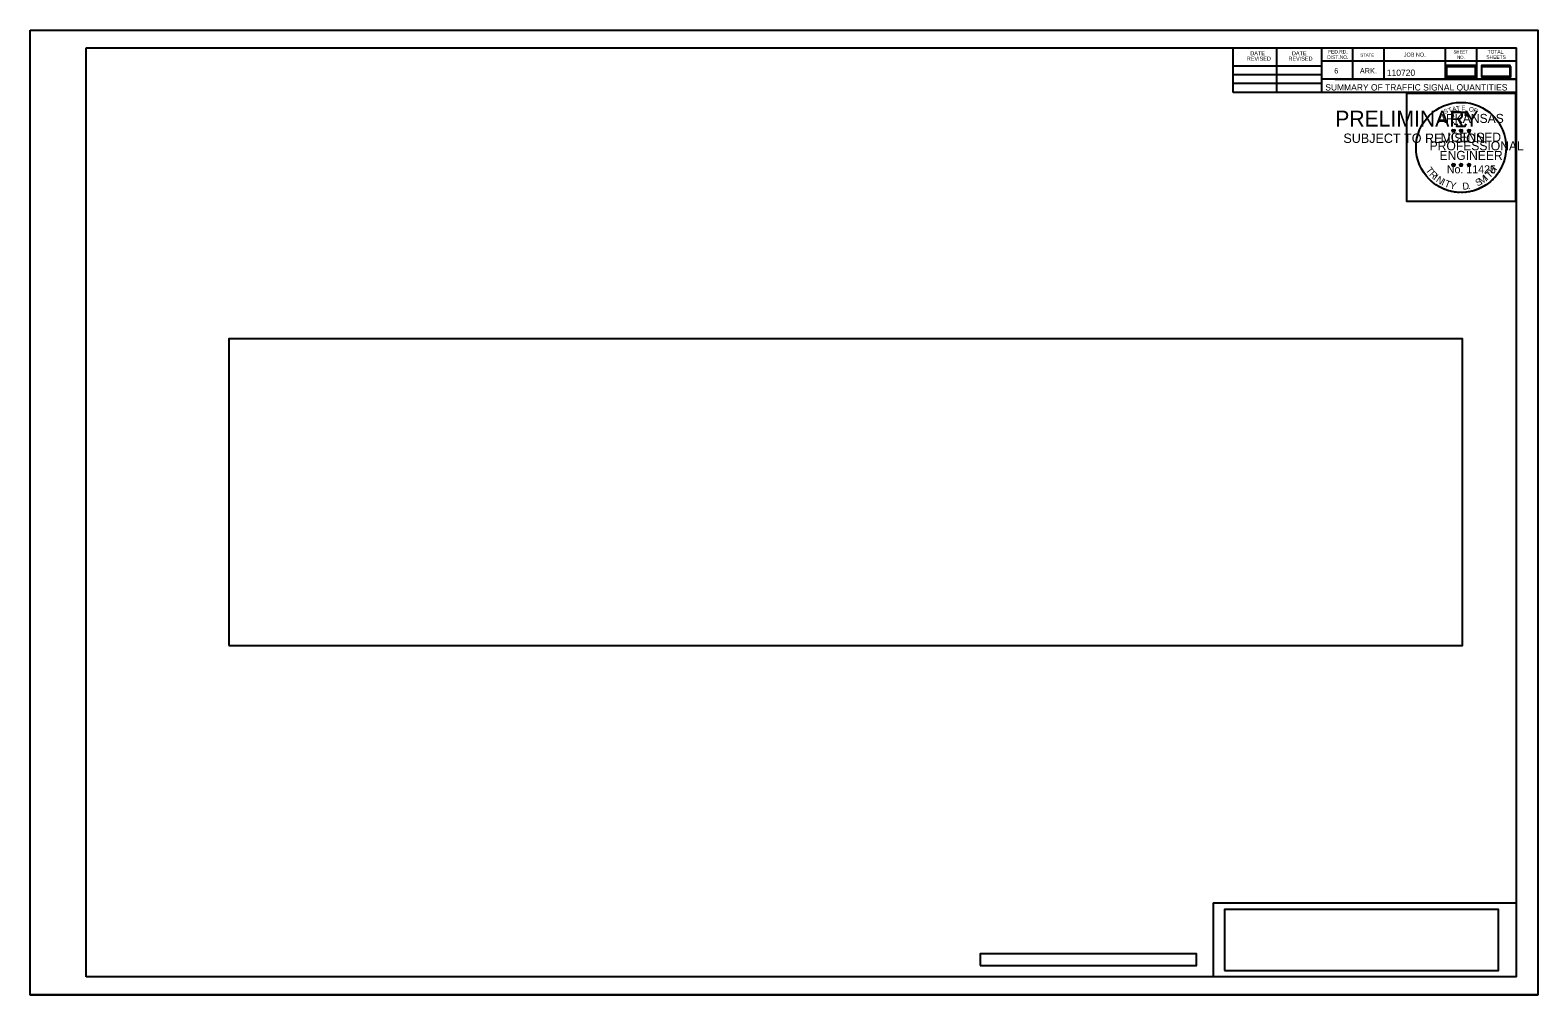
# Model space of a CAD drawing. Extents: x 1370022 to 1370689, y 379972 to 380399.
import ezdxf

# ---------------------------------------------------------------- set-up
doc = ezdxf.new("R2010")
doc.units = 0
for name, color, linetype in [('Default', 7, 'Continuous'), ('Level 1', 7, 'Continuous'), ('Level 2', 7, 'Continuous'), ('Level 3', 7, 'Continuous'), ('Level 4', 7, 'Continuous'), ('Level 5', 7, 'Continuous'), ('Level 6', 7, 'Continuous')]:
    doc.layers.add(name, color=color, linetype=linetype)

msp = doc.modelspace()

# ---------------------------------------------------------------- linework, layer by layer
at = {"layer": 'Default'}
for points in [[(1370648.78, 380378.37), (1370661.48, 380378.37), (1370661.48, 380383.06), (1370648.78, 380383.06)], [(1370664.17, 380378.37), (1370676.87, 380378.37), (1370676.87, 380383.06), (1370664.17, 380383.06)], [(1370110.3, 380126.54), (1370655.8, 380126.54), (1370655.8, 380262.2), (1370110.3, 380262.2)], [(1370550.63, 379982.78), (1370671.67, 379982.78), (1370671.67, 380009.76), (1370550.63, 380009.76)], [(1370442.54, 379985.01), (1370538.24, 379985.01), (1370538.24, 379990.18), (1370442.54, 379990.18)]]:
    msp.add_lwpolyline(points, close=True, dxfattribs=at)
at = {"layer": 'Level 1'}
for points in [[(1370545.57, 380012.69), (1370679.62, 380012.69)], [(1370545.57, 380012.69), (1370545.57, 379980)]]:
    msp.add_lwpolyline(points, dxfattribs=at)
at = {"layer": 'Level 2'}
for p, q in [((1370047.26, 380390.92), (1370679.62, 380390.92)), ((1370047.26, 379980), (1370047.26, 380390.92)), ((1370352.3, 380390.4), (1370352.3, 380390.4)), ((1370352.3, 380390.4), (1370352.3, 380390.4)), ((1370554.34, 380371.16), (1370554.34, 380390.92)), ((1370573.7, 380371.16), (1370573.7, 380390.92)), ((1370593.42, 380390.92), (1370593.42, 380371.16)), ((1370607.1, 380390.92), (1370607.1, 380377.04)), ((1370620.98, 380390.92), (1370620.98, 380377.04)), ((1370648.14, 380390.92), (1370648.14, 380377.04)), ((1370662.02, 380390.92), (1370662.02, 380377.04)), ((1370679.62, 379980), (1370679.62, 380390.92)), ((1370554.34, 380382.88), (1370593.42, 380382.88)), ((1370679.62, 380385.04), (1370593.42, 380385.04)), ((1370679.62, 380385.08), (1370679.62, 380385.08)), ((1370554.34, 380379.16), (1370593.42, 380379.16)), ((1370554.34, 380375.28), (1370593.42, 380375.28)), ((1370679.62, 380377.04), (1370593.42, 380377.04)), ((1370599.34, 380377.04), (1370679.62, 380377.04)), ((1370679.62, 380371.16), (1370554.34, 380371.16)), ((1370047.26, 379980), (1370047.26, 379980)), ((1370679.62, 379980), (1370047.26, 379980))]:
    msp.add_line(p, q, dxfattribs=at)
at = {"layer": 'Level 3'}
for p, q in [((1370022.46, 380398.71), (1370689.12, 380398.71)), ((1370631.03, 380325.07), (1370631.03, 380325.07)), ((1370022.46, 379972.05), (1370689.12, 379972.05))]:
    msp.add_line(p, q, dxfattribs=at)
for points in [[(1370022.44, 380398.71), (1370689.12, 380398.71), (1370689.12, 379972.04), (1370022.44, 379972.04)], [(1370631.18, 380370.86), (1370679.18, 380370.86), (1370679.18, 380322.86), (1370631.18, 380322.86)]]:
    msp.add_lwpolyline(points, close=True, dxfattribs=at)
msp.add_circle((1370655.18, 380346.86), 19.9, dxfattribs=at)
at = {"layer": 'Level 5'}
for p, q in [((1370651.13, 380354.49), (1370651.83, 380354.26)), ((1370651.13, 380354.49), (1370651.64, 380354.4)), ((1370651.13, 380354.49), (1370651.6, 380354.24)), ((1370651.83, 380354.99), (1370651.75, 380354.49)), ((1370651.83, 380354.26), (1370651.83, 380354.99)), ((1370651.83, 380354.99), (1370651.93, 380354.49)), ((1370652.52, 380354.49), (1370651.83, 380354.26)), ((1370652.52, 380354.49), (1370651.95, 380354.39)), ((1370652.52, 380354.49), (1370652.11, 380354.28)), ((1370654.47, 380354.49), (1370655.17, 380354.26)), ((1370654.47, 380354.49), (1370654.98, 380354.4)), ((1370654.47, 380354.49), (1370654.94, 380354.24)), ((1370655.17, 380354.99), (1370655.09, 380354.49)), ((1370655.17, 380354.26), (1370655.17, 380354.99)), ((1370655.17, 380354.99), (1370655.27, 380354.49)), ((1370655.86, 380354.49), (1370655.17, 380354.26)), ((1370655.86, 380354.49), (1370655.29, 380354.39)), ((1370655.86, 380354.49), (1370655.45, 380354.28)), ((1370658, 380354.46), (1370658.7, 380354.24)), ((1370658, 380354.46), (1370658.5, 380354.37)), ((1370658, 380354.46), (1370658.47, 380354.22)), ((1370658.7, 380354.97), (1370658.61, 380354.47)), ((1370658.7, 380354.24), (1370658.7, 380354.97)), ((1370658.7, 380354.97), (1370658.79, 380354.47)), ((1370659.39, 380354.46), (1370658.7, 380354.24)), ((1370659.39, 380354.46), (1370658.82, 380354.36)), ((1370659.39, 380354.46), (1370658.98, 380354.26)), ((1370651.4, 380353.67), (1370651.83, 380354.26)), ((1370651.4, 380353.67), (1370651.65, 380354.16)), ((1370651.4, 380353.67), (1370651.82, 380354.1)), ((1370652.25, 380353.67), (1370651.82, 380354.1)), ((1370652.25, 380353.67), (1370651.83, 380354.26)), ((1370652.25, 380353.67), (1370651.98, 380354.25)), ((1370654.74, 380353.67), (1370655.17, 380354.26)), ((1370654.74, 380353.67), (1370654.99, 380354.16)), ((1370654.74, 380353.67), (1370655.16, 380354.1)), ((1370655.59, 380353.67), (1370655.16, 380354.1)), ((1370655.59, 380353.67), (1370655.17, 380354.26)), ((1370655.59, 380353.67), (1370655.32, 380354.25)), ((1370658.26, 380353.65), (1370658.7, 380354.24)), ((1370658.26, 380353.65), (1370658.52, 380354.13)), ((1370658.26, 380353.65), (1370658.69, 380354.08)), ((1370659.12, 380353.65), (1370658.69, 380354.07)), ((1370659.12, 380353.65), (1370658.7, 380354.24)), ((1370659.12, 380353.65), (1370658.85, 380354.23)), ((1370651.12, 380339.34), (1370651.82, 380339.12)), ((1370651.12, 380339.34), (1370651.63, 380339.25)), ((1370651.12, 380339.34), (1370651.6, 380339.1)), ((1370651.39, 380338.52), (1370651.82, 380339.12)), ((1370651.39, 380338.52), (1370651.64, 380339.01)), ((1370651.39, 380338.52), (1370651.82, 380338.96)), ((1370651.82, 380339.85), (1370651.74, 380339.34)), ((1370651.82, 380339.12), (1370651.82, 380339.85)), ((1370651.82, 380339.85), (1370651.92, 380339.35)), ((1370652.51, 380339.34), (1370651.82, 380339.12)), ((1370652.25, 380338.52), (1370651.82, 380339.12)), ((1370652.25, 380338.52), (1370651.82, 380338.95)), ((1370652.51, 380339.34), (1370651.94, 380339.24)), ((1370652.25, 380338.52), (1370651.97, 380339.11)), ((1370652.51, 380339.34), (1370652.11, 380339.14)), ((1370654.46, 380339.34), (1370655.16, 380339.12)), ((1370654.46, 380339.34), (1370654.97, 380339.25)), ((1370654.46, 380339.34), (1370654.93, 380339.1)), ((1370654.73, 380338.52), (1370655.16, 380339.12)), ((1370654.73, 380338.52), (1370654.98, 380339.01)), ((1370654.73, 380338.52), (1370655.15, 380338.96)), ((1370655.16, 380339.85), (1370655.08, 380339.34)), ((1370655.58, 380338.52), (1370655.15, 380338.95)), ((1370655.16, 380339.12), (1370655.16, 380339.85)), ((1370655.16, 380339.85), (1370655.26, 380339.35)), ((1370655.85, 380339.34), (1370655.16, 380339.12)), ((1370655.58, 380338.52), (1370655.16, 380339.12)), ((1370655.85, 380339.34), (1370655.28, 380339.24)), ((1370655.58, 380338.52), (1370655.31, 380339.11)), ((1370655.85, 380339.34), (1370655.44, 380339.14)), ((1370657.99, 380339.32), (1370658.69, 380339.1)), ((1370657.99, 380339.32), (1370658.5, 380339.23)), ((1370657.99, 380339.32), (1370658.47, 380339.08)), ((1370658.26, 380338.5), (1370658.69, 380339.1)), ((1370658.26, 380338.5), (1370658.51, 380338.99)), ((1370658.26, 380338.5), (1370658.69, 380338.94)), ((1370658.69, 380339.83), (1370658.61, 380339.32)), ((1370658.69, 380339.1), (1370658.69, 380339.83)), ((1370658.69, 380339.83), (1370658.79, 380339.33)), ((1370659.39, 380339.32), (1370658.69, 380339.1)), ((1370659.12, 380338.5), (1370658.69, 380339.1)), ((1370659.12, 380338.5), (1370658.69, 380338.93)), ((1370659.39, 380339.32), (1370658.81, 380339.22)), ((1370659.12, 380338.5), (1370658.84, 380339.09)), ((1370659.39, 380339.32), (1370658.98, 380339.12))]:
    msp.add_line(p, q, dxfattribs=at)
for points in [[(1370651.21, 380362.24), (1370651.75, 380360.59)], [(1370658.23, 380360.4), (1370658.52, 380360.97), (1370657.15, 380360.92), (1370657.44, 380362.24), (1370651.21, 380362.24)], [(1370651.83, 380354.99), (1370652.25, 380353.67), (1370651.13, 380354.49), (1370652.52, 380354.49), (1370651.4, 380353.67), (1370651.83, 380354.99)], [(1370652.2, 380357.4), (1370652.2, 380357.22), (1370653.32, 380357.18), (1370653.21, 380356.24), (1370656.95, 380356.24), (1370657.36, 380357.31)], [(1370655.17, 380354.99), (1370655.59, 380353.67), (1370654.47, 380354.49), (1370655.86, 380354.49), (1370654.74, 380353.67), (1370655.17, 380354.99)], [(1370658.7, 380354.97), (1370659.12, 380353.65), (1370658, 380354.46), (1370659.39, 380354.46), (1370658.26, 380353.65), (1370658.7, 380354.97)], [(1370651.82, 380339.85), (1370652.25, 380338.52), (1370651.12, 380339.34), (1370652.51, 380339.34), (1370651.39, 380338.52), (1370651.82, 380339.85)], [(1370655.16, 380339.85), (1370655.58, 380338.52), (1370654.46, 380339.34), (1370655.85, 380339.34), (1370654.73, 380338.52), (1370655.16, 380339.85)], [(1370658.69, 380339.83), (1370659.12, 380338.5), (1370657.99, 380339.32), (1370659.39, 380339.32), (1370658.26, 380338.5), (1370658.69, 380339.83)]]:
    msp.add_lwpolyline(points, dxfattribs=at)
for centre, radius in [((1370651.83, 380354.26), 0.344), ((1370651.83, 380354.26), 0.289), ((1370651.83, 380354.26), 0.231), ((1370651.83, 380354.26), 0.198), ((1370651.83, 380354.26), 0.149), ((1370651.83, 380354.26), 0.0991), ((1370651.83, 380354.26), 0.0593), ((1370655.17, 380354.26), 0.344), ((1370655.17, 380354.26), 0.289), ((1370655.17, 380354.26), 0.231), ((1370655.17, 380354.26), 0.198), ((1370655.17, 380354.26), 0.149), ((1370655.17, 380354.26), 0.0991), ((1370655.17, 380354.26), 0.0593), ((1370658.69, 380354.24), 0.344), ((1370658.69, 380354.24), 0.289), ((1370658.69, 380354.24), 0.231), ((1370658.69, 380354.24), 0.198), ((1370658.69, 380354.24), 0.149), ((1370658.69, 380354.24), 0.0991), ((1370658.69, 380354.24), 0.0593), ((1370651.82, 380339.12), 0.344), ((1370651.82, 380339.12), 0.289), ((1370651.82, 380339.12), 0.231), ((1370651.82, 380339.12), 0.198), ((1370651.82, 380339.12), 0.149), ((1370651.82, 380339.12), 0.0991), ((1370651.82, 380339.12), 0.0593), ((1370655.16, 380339.12), 0.344), ((1370655.16, 380339.12), 0.289), ((1370655.16, 380339.12), 0.231), ((1370655.16, 380339.12), 0.198), ((1370655.16, 380339.12), 0.149), ((1370655.16, 380339.12), 0.0991), ((1370655.16, 380339.12), 0.0593), ((1370658.69, 380339.1), 0.344), ((1370658.69, 380339.1), 0.289), ((1370658.69, 380339.1), 0.231), ((1370658.69, 380339.1), 0.198), ((1370658.69, 380339.1), 0.149), ((1370658.69, 380339.1), 0.0991), ((1370658.69, 380339.1), 0.0593)]:
    msp.add_circle(centre, radius, dxfattribs=at)
at = {"layer": 'Level 6'}
for points in [[(1370648.76, 380382.58), (1370661.45, 380382.58), (1370661.45, 380377.89), (1370648.76, 380377.89)], [(1370664.39, 380382.58), (1370677.09, 380382.58), (1370677.09, 380377.89), (1370664.39, 380377.89)]]:
    msp.add_lwpolyline(points, close=True, dxfattribs=at)

# ---------------------------------------------------------------- texts
at = {"layer": 'Level 2'}
for s, height, p in [('DATE', 1.758, (1370561.98, 380387.6)), ('DATE', 1.758, (1370580.39, 380387.6)), ('FED.RD.', 1.564, (1370596.38, 380388.36)), ('STATE', 1.368, (1370610.62, 380387)), ('JOB NO.', 1.758, (1370629.82, 380387)), ('SHEET', 1.368, (1370651.86, 380388.36)), ('TOTAL', 1.564, (1370666.9, 380388.36)), ('REVISED', 1.758, (1370560.42, 380385.24)), ('REVISED', 1.758, (1370578.83, 380385.24)), ('DIST.NO.', 1.564, (1370595.98, 380386)), ('6', 2.34, (1370599.1, 380379.56)), ('ARK.', 2.345, (1370610.42, 380379.56)), ('110720', 2.8, (1370622.37, 380378.48)), ('NO.', 1.368, (1370653.42, 380386)), ('SHEETS', 1.564, (1370666.34, 380386)), ('SUMMARY OF TRAFFIC SIGNAL QUANTITIES', 2.8, (1370595.14, 380372.02))]:
    msp.add_text(s, height=height, dxfattribs=at).set_placement(p)
at = {"layer": 'Level 4'}
for s, height, p in [('PRELIMINARY', 7, (1370599.52, 380356.09)), ('SUBJECT TO REVISION', 4.1502, (1370603.14, 380348.83))]:
    msp.add_text(s, height=height, dxfattribs=at).set_placement(p)
at = {"layer": 'Level 5'}
for s, height, rotation, p in [('-', 3.2, 48.42305, (1370641.11, 380359.25)), ('-', 3.2, 42.96224, (1370642.01, 380360.2)), ('-', 3.2, 38.95066, (1370642.87, 380361.04)), ('-', 3.2, 36.23174, (1370643.82, 380361.79)), ('-', 3.2, 34.06357, (1370644.98, 380362.58)), ('-', 3.2, 28.79182, (1370646.17, 380363.32)), ('-', 3.2, 24.30721, (1370647.44, 380363.96)), ('S', 2, 21.59401, (1370647.92, 380361.6)), ('-', 3.2, 19.17608, (1370648.71, 380364.5)), ('T', 2, 16.4036, (1370649.75, 380362.26)), ('-', 3.2, 13.63015, (1370650.21, 380364.98)), ('A', 2, 11.21318, (1370651.4, 380362.76)), ('-', 3.2, 10.21935, (1370651.56, 380365.3)), ('T', 2, 6.02276, (1370653.1, 380363.09)), ('-', 3.2, 5.89682, (1370653.02, 380365.52)), ('-', 3.2, 0.18623, (1370654.57, 380365.67)), ('E', 2, 0.83234, (1370655.31, 380363.31)), ('-', 3.2, 357.74304, (1370656.01, 380365.64)), ('-', 3.2, 352.16172, (1370657.5, 380365.53)), ('O', 2, 350.4515, (1370658.52, 380362.89)), ('-', 3.2, 347.20489, (1370658.94, 380365.3)), ('F', 2, 340.07066, (1370660.43, 380362.44)), ('-', 3.2, 342.3362, (1370660.21, 380364.99)), ('-', 3.2, 337.85509, (1370661.68, 380364.54)), ('-', 3.2, 334.12109, (1370662.94, 380364)), ('-', 3.2, 329.64089, (1370664.1, 380363.44)), ('-', 3.2, 325.86266, (1370665.38, 380362.71)), ('-', 3.2, 320.52971, (1370666.6, 380361.86)), ('-', 3.2, 315.57859, (1370667.8, 380360.89)), ('-', 3.2, 67.77427, (1370637.68, 380353.64)), ('-', 3.2, 62.87135, (1370638.2, 380354.86)), ('-', 3.2, 58.07063, (1370638.83, 380356.09)), ('-', 3.2, 54.23247, (1370639.48, 380357.14)), ('-', 3.2, 50.61417, (1370640.3, 380358.28)), ('-', 3.2, 309.87973, (1370668.94, 380359.79)), ('-', 3.2, 306.65218, (1370669.99, 380358.58)), ('-', 2.8, 303.67529, (1370670.96, 380357.45)), ('-', 3.2, 299.66835, (1370671.6, 380356.23)), ('-', 3.2, 294.66279, (1370672.25, 380355.01)), ('-', 3.2, 89.06224, (1370636.39, 380346.74)), ('-', 3.2, 85.18634, (1370636.44, 380348.14)), ('-', 3.2, 81.20126, (1370636.59, 380349.52)), ('-', 3.2, 75.46096, (1370636.85, 380350.95)), ('-', 3.2, 72.39447, (1370637.25, 380352.38)), ('-', 3.2, 290.57283, (1370672.76, 380353.85)), ('-', 3.2, 285.12326, (1370673.23, 380352.69)), ('-', 3.2, 280.54934, (1370673.63, 380351.21)), ('-', 3.2, 276.59616, (1370673.95, 380349.67)), ('-', 3.2, 274.33011, (1370674.07, 380348.23)), ('-', 3.2, 94.19588, (1370636.46, 380345.29)), ('-', 3.2, 98.94793, (1370636.6, 380343.96)), ('-', 3.2, 101.71495, (1370636.87, 380342.49)), ('-', 3.2, 105.45785, (1370637.19, 380341.3)), ('-', 3.2, 252.86809, (1370673.38, 380341.53)), ('-', 3.2, 255.7626, (1370673.74, 380342.97)), ('-', 3.2, 260.99529, (1370673.96, 380344.33)), ('-', 3.2, 263.5172, (1370674.1, 380345.63)), ('-', 3.2, 269.94067, (1370674.14, 380346.97)), ('-', 3.2, 109.08742, (1370637.62, 380340.04)), ('-', 3.2, 114.06432, (1370638.13, 380338.85)), ('-', 3.2, 115.72885, (1370638.74, 380337.61)), ('-', 3.2, 120.44712, (1370639.46, 380336.44)), ('-', 3.2, 125.89344, (1370640.26, 380335.32)), ('-', 3.2, 130.71812, (1370641.19, 380334.21)), ('T', 3.08, 306.04056, (1370639.34, 380336.79)), ('R', 3.08, 314.00497, (1370640.86, 380334.7)), ('I', 3.08, 321.96938, (1370642.66, 380332.84)), ('N', 3.08, 326.50021, (1370643.8, 380331.89)), ('M', 3.08, 32.65632, (1370664.11, 380330.33)), ('I', 3.08, 42.11359, (1370666.68, 380332.02)), ('T', 3.08, 46.64442, (1370667.8, 380332.98)), ('H', 3.08, 54.60883, (1370669.58, 380334.87)), ('-', 3.2, 233.84524, (1370670.82, 380336.12)), ('-', 3.2, 239.07125, (1370671.62, 380337.42)), ('-', 3.2, 244.61971, (1370672.41, 380338.93)), ('-', 3.2, 247.88866, (1370672.93, 380340.18)), ('-', 3.2, 134.22381, (1370642.22, 380333.12)), ('-', 3.2, 138.93382, (1370643.27, 380332.19)), ('-', 3.2, 144.64634, (1370644.38, 380331.38)), ('-', 3.2, 148.08978, (1370645.5, 380330.64)), ('-', 3.2, 151.57039, (1370646.66, 380329.99)), ('-', 3.2, 154.60019, (1370647.71, 380329.5)), ('I', 3.08, 335.36034, (1370646.22, 380330.32)), ('-', 3.2, 158.56121, (1370648.95, 380328.99)), ('T', 3.08, 339.89117, (1370647.54, 380329.67)), ('-', 3.2, 162.79826, (1370650.33, 380328.56)), ('Y', 3.08, 347.85558, (1370649.97, 380328.77)), ('D', 3.08, 6.39691, (1370655.94, 380328.06)), ('.', 3.08, 13.76417, (1370658.33, 380328.31)), ('-', 3.2, 195.47429, (1370660.83, 380328.76)), ('-', 3.2, 200.71842, (1370662.19, 380329.24)), ('S', 3.08, 26.9312, (1370662.43, 380329.52)), ('-', 3.2, 204.25161, (1370663.43, 380329.79)), ('-', 3.2, 207.35684, (1370664.67, 380330.43)), ('-', 3.2, 212.24909, (1370665.79, 380331.12)), ('-', 3.2, 215.73633, (1370666.86, 380331.89)), ('-', 3.2, 221.08509, (1370667.96, 380332.84)), ('-', 3.2, 225.76533, (1370669, 380333.86)), ('-', 3.2, 231.25377, (1370669.96, 380334.98)), ('-', 3.2, 167.55551, (1370651.76, 380328.23)), ('-', 3.2, 173.11546, (1370653.3, 380328.01)), ('-', 3.2, 176.51827, (1370654.8, 380327.91)), ('-', 3.2, 181.59176, (1370656.29, 380327.95)), ('-', 3.2, 185.81666, (1370657.9, 380328.1)), ('-', 3.2, 191.28576, (1370659.38, 380328.36))]:
    msp.add_text(s, height=height, rotation=rotation, dxfattribs=at).set_placement(p)
for s, height, p in [('ARKANSAS', 4, (1370644.92, 380357.67)), ('DWB', 0.02, (1370651.8, 380354.25)), ('DWB', 0.02, (1370655.14, 380354.25)), ('PROFESSIONAL', 4, (1370641.27, 380345.56)), ('LICENSED', 4, (1370646.11, 380349.37)), ('DWB', 0.02, (1370658.67, 380354.23)), ('ENGINEER', 4, (1370645.64, 380341.31)), ('No. 11425', 3.514, (1370648.89, 380335.41)), ('DWB', 0.02, (1370651.79, 380339.11)), ('DWB', 0.02, (1370655.13, 380339.11)), ('DWB', 0.02, (1370658.67, 380339.09))]:
    msp.add_text(s, height=height, dxfattribs=at).set_placement(p)

doc.saveas('drawing.dxf')
